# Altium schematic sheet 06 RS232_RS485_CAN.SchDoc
size 297 x 209 mm
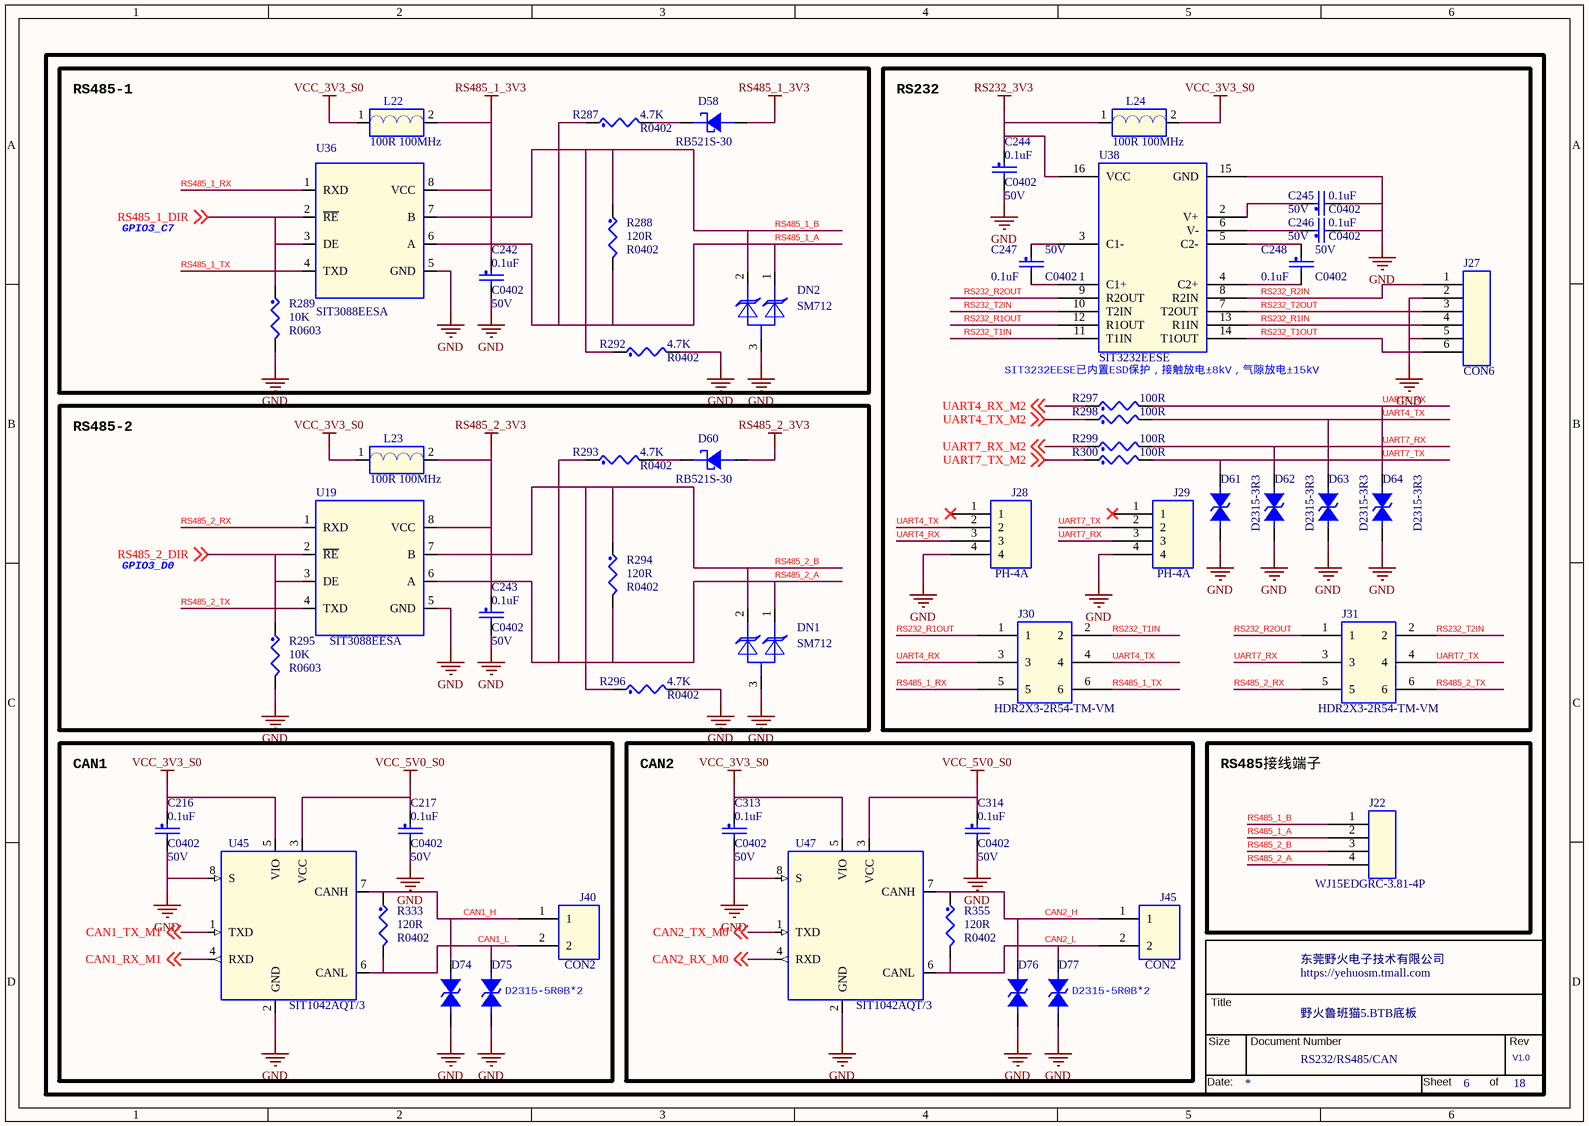
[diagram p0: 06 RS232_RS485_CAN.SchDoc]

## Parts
*  Doc: RS232/RS485/CAN  RevCode: V1.0  Title: 野火鲁班猫5.BTB底板  OrgName: 东莞野火电子技术有限公司  Page Number: 6  Page Count: 18  (hidden comment: TitleBlock_YHSCH)  (graphical)
C216  0.1uF  Voltage: 50V  [C0402]
C217  0.1uF  Voltage: 50V  [C0402]
C242  0.1uF  Voltage: 50V  [C0402]
C243  0.1uF  Voltage: 50V  [C0402]
C244  0.1uF  Voltage: 50V  [C0402]
C245  0.1uF  Voltage: 50V  [C0402]
C246  0.1uF  Voltage: 50V  [C0402]
C247  0.1uF  Voltage: 50V  [C0402]
C248  0.1uF  Voltage: 50V  [C0402]
C313  0.1uF  Voltage: 50V  [C0402]
C314  0.1uF  Voltage: 50V  [C0402]
D58  RB521S-30  [SOD523]
D60  RB521S-30  [SOD523]
D61  D2315-3R3  [D0603/SMD]
D62  D2315-3R3  [D0603/SMD]
D63  D2315-3R3  [D0603/SMD]
D64  D2315-3R3  [D0603/SMD]
D74  D2315-5R0B  [D0603/SMD]  (value not drawn)
D75  D2315-5R0B  [D0603/SMD]  (value not drawn)
D76  D2315-5R0B  [D0603/SMD]  (value not drawn)
D77  D2315-5R0B  [D0603/SMD]  (value not drawn)
DN1  SM712  [SOT23]
DN2  SM712  [SOT23]
J22  WJ15EDGRC-3.81-4P  [DB2ERC-3P81-4P]
J27  CON6  [DB2ERC-3P81-6P]
J28  PH-4A  [PH-1X4-2P0]
J29  PH-4A  [PH-1X4-2P0]
J30  HDR2X3-2R54-TM-VM  [HDR2X3-2R54-TM-VM]
J31  HDR2X3-2R54-TM-VM  [HDR2X3-2R54-TM-VM]
J40  CON2  [db2erc-3p81-2p]
J45  CON2  [db2erc-3p81-2p]
L22  100R 100MHz  [L0603]
L23  100R 100MHz  [L0603]
L24  100R 100MHz  [L0603]
R287  4.7K  [R0402]
R288  120R  [R0402]
R289  10K  [R0603]
R292  4.7K  [R0402]
R293  4.7K  [R0402]
R294  120R  [R0402]
R295  10K  [R0603]
R296  4.7K  [R0402]
R297  100R  [R0402]
R298  100R  [R0402]
R299  100R  [R0402]
R300  100R  [R0402]
R333  120R  [R0402]
R355  120R  [R0402]
U19  SIT3088EESA  [SOP8]
U36  SIT3088EESA  [SOP8]
U38  SIT3232EESE  [16]
U45  SIT1042AQT/3  [SOP8]
U47  SIT1042AQT/3  [SOP8]

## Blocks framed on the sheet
RS485-1: C242 D58 DN2 L22 R287-R289 R292 U36
RS232: C244-C248 D61-D64 J27-J31 L24 R297-R300 U38
RS485-2: C243 D60 DN1 L23 R293-R296 U19
CAN1: C216 C217 D74 D75 J40 R333 U45
CAN2: C313 C314 D76 D77 J45 R355 U47
RS485接线端子: J22

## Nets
GND: C216.2 C217.2 C242.2 C243.2 C244.2 C245.2 C246.2 C313.2 C314.2 D61.2 D62.2 D63.2 D64.2 D74.1 D75.1 D76.1 D77.1 DN1.3(A) DN2.3(A) J27.2 J27.5 J28.4 J29.4 R289.2 R292.2 R295.2 R296.2 U19.5(GND) U36.5(GND) U38.15(GND) U45.2(GND) U45.8(S) U47.2(GND) U47.8(S)
RS232_3V3: C244.1 L24.1 U38.16(VCC)
RS485_1_3V3: C242.1 D58.2 L22.2 U36.8(VCC)
RS485_2_3V3: C243.1 D60.2 L23.2 U19.8(VCC)
VCC_3V3_S0: C216.1 C313.1 L22.1 L23.1 L24.2 U45.5(VIO) U47.5(VIO)
VCC_5V0_S0: C217.1 C314.1 U45.3(VCC) U47.3(VCC)
CAN1_H: D74.2 J40.1 R333.1 U45.7(CANH)
CAN1_L: D75.2 J40.2 R333.2 U45.6(CANL)
CAN1_RX_M1: U45.4(RXD) ; off-sheet CAN1_RX_M1
CAN1_TX_M1: U45.1(TXD) ; off-sheet CAN1_TX_M1
CAN2_H: D76.2 J45.1 R355.1 U47.7(CANH)
CAN2_L: D77.2 J45.2 R355.2 U47.6(CANL)
CAN2_RX_M0: U47.4(RXD) ; off-sheet CAN2_RX_M0
CAN2_TX_M0: U47.1(TXD) ; off-sheet CAN2_TX_M0
RS232_R1IN: J27.4 U38.13(R1IN)
RS232_R1OUT: J30.1 U38.12(R1OUT)
RS232_R2IN: J27.1 U38.8(R2IN)
RS232_R2OUT: J31.1 U38.9(R2OUT)
RS232_T1IN: J30.2 U38.11(T1IN)
RS232_T1OUT: J27.6 U38.14(T1OUT)
RS232_T2IN: J31.2 U38.10(T2IN)
RS232_T2OUT: J27.3 U38.7(T2OUT)
RS485_1_A: DN2.1(C1) J22.2 R287.1 R288.2 U36.6(A)
RS485_1_B: DN2.2(C2) J22.1 R288.1 R292.1 U36.7(B)
RS485_1_DIR: R289.1 U36.2(~{RE}) U36.3(DE) ; off-sheet RS485_1_DIR
RS485_1_RX: J30.5 U36.1(RXD)
RS485_1_TX: J30.6 U36.4(TXD)
RS485_2_A: DN1.1(C1) J22.4 R293.1 R294.2 U19.6(A)
RS485_2_B: DN1.2(C2) J22.3 R294.1 R296.1 U19.7(B)
RS485_2_DIR: R295.1 U19.2(~{RE}) U19.3(DE) ; off-sheet RS485_2_DIR
RS485_2_RX: J31.5 U19.1(RXD)
RS485_2_TX: J31.6 U19.4(TXD)
UART4_RX: D61.1 D62.1 D63.1 D64.1 J28.2 J28.3 J29.2 J29.3 J30.3 J30.4 J31.3 J31.4 R297.2 R298.2 R299.2 R300.2  [also labelled UART4_TX, UART7_RX, UART7_TX]
UART4_RX_M2: R297.1 ; off-sheet UART4_RX_M2
UART4_TX_M2: R298.1 ; off-sheet UART4_TX_M2
UART7_RX_M2: R299.1 ; off-sheet UART7_RX_M2
UART7_TX_M2: R300.1 ; off-sheet UART7_TX_M2
NetC245_1: C245.1 U38.2(V+)
NetC246_1: C246.1 U38.6(V-)
NetC247_1: C247.1 U38.3(C1-)
NetC247_2: C247.2 U38.1(C1+)
NetC248_1: C248.1 U38.5(C2-)
NetC248_2: C248.2 U38.4(C2+)
NetD58_1: D58.1 R287.2
NetD60_1: D60.1 R293.2

Not connected (* = marked no-connect by the designer): J28 1*; J29 1*

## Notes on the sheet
- GPIO3_C7
- SIT3232EESE已内置ESD保护，接触放电±8kV，气隙放电±15kV
- GPIO3_D0
- (near D75) D2315-5R0B*2
- (near D77) D2315-5R0B*2

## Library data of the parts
* = TitleBlock_YHSCH: Cage Code: 1
C216 C217 C242 C244-C246 C313 C314 = CAP_NP: CLASS: DISCRETE; 规格: 贴片电容0.1uF 10% 50V X5R 0402; 规格编号: 0402X104K500NT; 条码: EBF29060118; 品牌: 风华; 类别: 贴片电容0402; 规格书: 风华电容.pdf; 价格: 0.029826; 生命周期: 量产
C243 C247 C248 = CAP_NP: CLASS: DISCRETE; 生命周期: 量产; 价格: 0.029826; 规格书: 风华电容.pdf; 类别: 贴片电容0402; 品牌: 风华; 条码: EBF29060118; 规格编号: 0402X104K500NT; 规格: 贴片电容0.1uF 10% 50V X5R 0402
D58 = DIODE_SCHTKY: CLASS: IC; 规格: 直流反向耐压(Vr)：30V 平均整流电流(Io)：200mA 正向压降(Vf)：500mV@200mA 30V@100mA,VF=350mV@10mA; 条码: EBFCIS221114153437; 品牌: 江苏长电; 类别: 贴片肖特基二极管; 规格书: 江苏长电_RB521S-30.pdf; 价格: 0.06781; 生命周期: 量产
D60 = DIODE_SCHTKY: CLASS: IC; 生命周期: 量产; 价格: 0.06781; 规格书: 江苏长电_RB521S-30.pdf; 类别: 贴片肖特基二极管; 品牌: 江苏长电; 条码: EBFCIS221114153437; 规格: 直流反向耐压(Vr)：30V 平均整流电流(Io)：200mA 正向压降(Vf)：500mV@200mA 30V@100mA,VF=350mV@10mA
D61-D64 = DIODE BI-DIR TRIG: 备注: 通用; 规格: 防静电保护ESD二极管 反向工作电压3.3V 击穿电压3.5V 钳位电压9V 结电容Cj 10pF; 条码: EBFCIS240517170749; 品牌: 千虹; 类别: 贴片ESD; 规格书: 千虹_D2315-3R3.pdf; 生命周期: 量产; PCB Footprint: esd0402
D74-D77 = DIODE BI-DIR TRIG: 备注: 通用; 生命周期: 量产; 规格书: 千虹_D2315-5R0B.pdf; 类别: 贴片ESD; 品牌: 千虹; 条码: EBFCIS240517170922; 规格: 防静电保护ESD二极管 反向工作电压5V 击穿电压7V 钳位电压10.5V 结电容Cj 0.3pF; PCB Footprint: esd0402
DN1 = TVS Arr ComA: 规格: 防静电保护ESD二极管 箝位电压12V -7V 击穿电压13.3V -7.5V; 条码: EBFCIS221015085507; 品牌: 时科; 类别: 贴片ESD; 规格书: 时科_SM712.pdf; 价格: 0.273512; 生命周期: 量产
DN2 = TVS Arr ComA: 生命周期: 量产; 价格: 0.273512; 规格书: 时科_SM712.pdf; 类别: 贴片ESD; 品牌: 时科; 条码: EBFCIS221015085507; 规格: 防静电保护ESD二极管 箝位电压12V -7V 击穿电压13.3V -7.5V
J22 = CON4: 规格: 插拔式接线端子 间距3.81mm 90度弯针 4PIN; 条码: EBF29040009; 品牌: 康奈克斯电气; 类别: 绿色插拔式接线端子; 规格书: 康奈克斯电气-绿色端子弯针插座.pdf; 价格: 0.198381; 生命周期: 量产
J27 = CON6: 规格: 绿色插拔式接线端子 间距3.81mm 90度弯针 6PIN; 规格编号: WJ15EDGRC-3.81-6P; 条码: EBF29040013; 品牌: 康奈克斯电气; 类别: 绿色插拔式接线端子; 规格书: 康奈克斯电气-绿色端子弯针插座.pdf; 价格: 0.301748; 生命周期: 量产
J28 J29 = 1X4PIN: 规格: 直针PH2.0-4P 间距2.0MM 拔插式 接插件; 条码: EBF29020025; 品牌: 博穆精密; 类别: PH连接器; 规格书: 博穆精密-PH2.0.pdf; 价格: 0.017; 生命周期: 量产
J30 J31 = 2X3PIN: 规格: 蓝色直插双排排针 总PIN数6 间距2.54mm; 规格编号: HDR2X3-2R54-TM-VM-BLUE; 条码: EBF29020030; 品牌: 州日; 类别: 2.54mm直插双排排针; 规格书: 州日_双排针_直插_2P54.pdf; 生命周期: 量产
J40 = CON2: 生命周期: 量产; 价格: 0.107525; 规格书: C8387_插针_板端弯针2P3.81MM_2019-12-25 .pdf; 类别: 绿色插拔式接线端子; 品牌: 康奈克斯电气; 条码: EBF29040070; 规格编号: WJ15EDGRC-3.81-2P; 规格: 绿色插拔式接线端子母座_2Pin  90度弯针 3.81间距
J45 = CON2: 规格: 绿色插拔式接线端子母座_2Pin  90度弯针 3.81间距; 规格编号: WJ15EDGRC-3.81-2P; 条码: EBF29040070; 品牌: 康奈克斯电气; 类别: 绿色插拔式接线端子; 规格书: C8387_插针_板端弯针2P3.81MM_2019-12-25 .pdf; 价格: 0.107525; 生命周期: 量产
L22 L24 = BEAD: CLASS: DISCRETE; 规格: 磁珠100Ω @100MHz 额定电流3A 直流电阻30mΩ; 规格编号: UPZ1608E101-3R0TF; 条码: EBF29050038; 品牌: 顺络; 类别: 贴片磁珠0603; 规格书: 顺络-磁珠.pdf; 价格: 0.021567; 生命周期: 量产
L23 = BEAD: CLASS: DISCRETE; 生命周期: 量产; 价格: 0.021567; 规格书: 顺络-磁珠.pdf; 类别: 贴片磁珠0603; 品牌: 顺络; 条码: EBF29050038; 规格编号: UPZ1608E101-3R0TF; 规格: 磁珠100Ω @100MHz 额定电流3A 直流电阻30mΩ
R287 R292 = RES: CLASS: DISCRETE; 规格: 贴片电阻4.7K 1% 1/16W 0402; 规格编号: RI0402L4701FT; 条码: EBF29070047; 品牌: 合科泰; 类别: 贴片电阻0402; 规格书: 合科泰-RI系列电阻.pdf; 生命周期: 量产
R288 R333 = RES: CLASS: DISCRETE; 价格: 0.002198; 规格: 贴片电阻120R 1% 1/16W 0402; 规格编号: 0402WGF1200TCE; 条码: EBF29070275; 品牌: 厚声; 类别: 贴片电阻0402; 规格书: 厚声-无铅厚膜电阻.pdf; 生命周期: 量产
R289 = RES: CLASS: DISCRETE; 生命周期: 量产; 规格书: 合科泰-RI系列电阻.pdf; 类别: 贴片电阻0603; 品牌: 合科泰; 条码: EBF29070074; 规格编号: RI0603L1002FT; 规格: 贴片电阻10K 1% 1/10W 0603
R293 R296 = RES: CLASS: DISCRETE; 生命周期: 量产; 规格书: 合科泰-RI系列电阻.pdf; 类别: 贴片电阻0402; 品牌: 合科泰; 条码: EBF29070047; 规格编号: RI0402L4701FT; 规格: 贴片电阻4.7K 1% 1/16W 0402
R294 = RES: CLASS: DISCRETE; 价格: 0.002198; 生命周期: 量产; 规格书: 厚声-无铅厚膜电阻.pdf; 类别: 贴片电阻0402; 品牌: 厚声; 条码: EBF29070275; 规格编号: 0402WGF1200TCE; 规格: 贴片电阻120R 1% 1/16W 0402
R295 = RES: CLASS: DISCRETE; 规格: 贴片电阻10K 1% 1/10W 0603; 规格编号: RI0603L1002FT; 条码: EBF29070074; 品牌: 合科泰; 类别: 贴片电阻0603; 规格书: 合科泰-RI系列电阻.pdf; 生命周期: 量产
R297-R300 = RES: CLASS: DISCRETE; 生命周期: 量产; 规格书: 合科泰-RI系列电阻.pdf; 类别: 贴片电阻0402; 品牌: 合科泰; 条码: EBF29070053; 规格编号: RI0402L1000FT; 规格: 贴片电阻100R 1% 1/16W 0402
R355 = RES: CLASS: DISCRETE; 生命周期: 量产; 规格书: 厚声-无铅厚膜电阻.pdf; 类别: 贴片电阻0402; 品牌: 厚声; 条码: EBF29070275; 规格编号: 0402WGF1200TCE; 规格: 贴片电阻120R 1% 1/16W 0402; 价格: 0.002198
U19 = SIT3088E-8P: CLASS: IC; 备注: 鲁班猫; 生命周期: 量产; 规格书: 芯力特_SIT3088E-V1.8_cn.pdf; 类别: RS485/RS422芯片; 品牌: 芯力特; 条码: EBFCIS231207153322; 规格: RS-485/RS-422芯片 收发器 允许256个器件连接总线 协议类别RS-485 电源电压3.0V~5.5V 数据速率14Mbps
U36 = SIT3088E-8P: CLASS: IC; 规格: RS-485/RS-422芯片 收发器 允许256个器件连接总线 协议类别RS-485 电源电压3.0V~5.5V 数据速率14Mbps; 条码: EBFCIS231207153322; 品牌: 芯力特; 类别: RS485/RS422芯片; 规格书: 芯力特_SIT3088E-V1.8_cn.pdf; 生命周期: 量产; 备注: 鲁班猫
U38 = MAX3232CSE: 规格: RS232芯片 收发器 驱动器/接收器数：2/2 协议类别RS232 电源电压3.0V~5.5V 数据速率96kbps; 条码: EBFCIS231207155139; 品牌: 芯力特; 类别: RS232芯片; 规格书: 芯力特_SIT3232E-V1.17-cn.pdf; 生命周期: 量产; 备注: 鲁班猫; PCB Footprint: SOIC16
U45 = TJA1057GT3_8P: CLASS: IC; 生命周期: 量产; 价格: 1.98; 规格书: 芯力特_SIT1042.pdf; 类别: CAN芯片; 品牌: 芯力特; 条码: EBFCIS230524153230; 规格: CAN芯片 收发器 驱动器/接收器数：1/1 协议类别CAN总线 电源电压4.5V~5.5V 数据速率5Mbps; 备注: 替代TJA1042T/3/1J
U47 = TJA1057GT3_8P: CLASS: IC; 备注: 替代TJA1042T/3/1J; 生命周期: 量产; 价格: 1.98; 规格书: 芯力特_SIT1042.pdf; 类别: CAN芯片; 品牌: 芯力特; 条码: EBFCIS230524153230; 规格: CAN芯片 收发器 驱动器/接收器数：1/1 协议类别CAN总线 电源电压4.5V~5.5V 数据速率5Mbps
